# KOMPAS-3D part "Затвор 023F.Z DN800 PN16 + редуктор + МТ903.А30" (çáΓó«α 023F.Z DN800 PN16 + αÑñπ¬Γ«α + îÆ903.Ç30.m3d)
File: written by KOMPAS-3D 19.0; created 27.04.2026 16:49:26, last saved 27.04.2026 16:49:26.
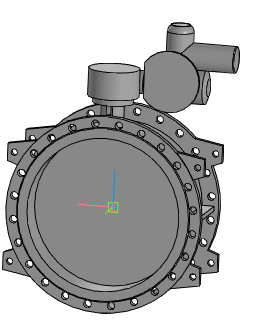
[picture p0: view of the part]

Document properties: Полное имя файла: ..\..\Затвор 023F.Z DN400-DN1600 + редуктор + МТ903\Затвор 023F.Z DN800 PN16 + редуктор + МТ903.А30.a3d

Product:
- Part/product: Затвор 023F.Z DN800 PN16 + редуктор + МТ903.А30
    Масса: 955.558

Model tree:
1. Операция без истории:1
